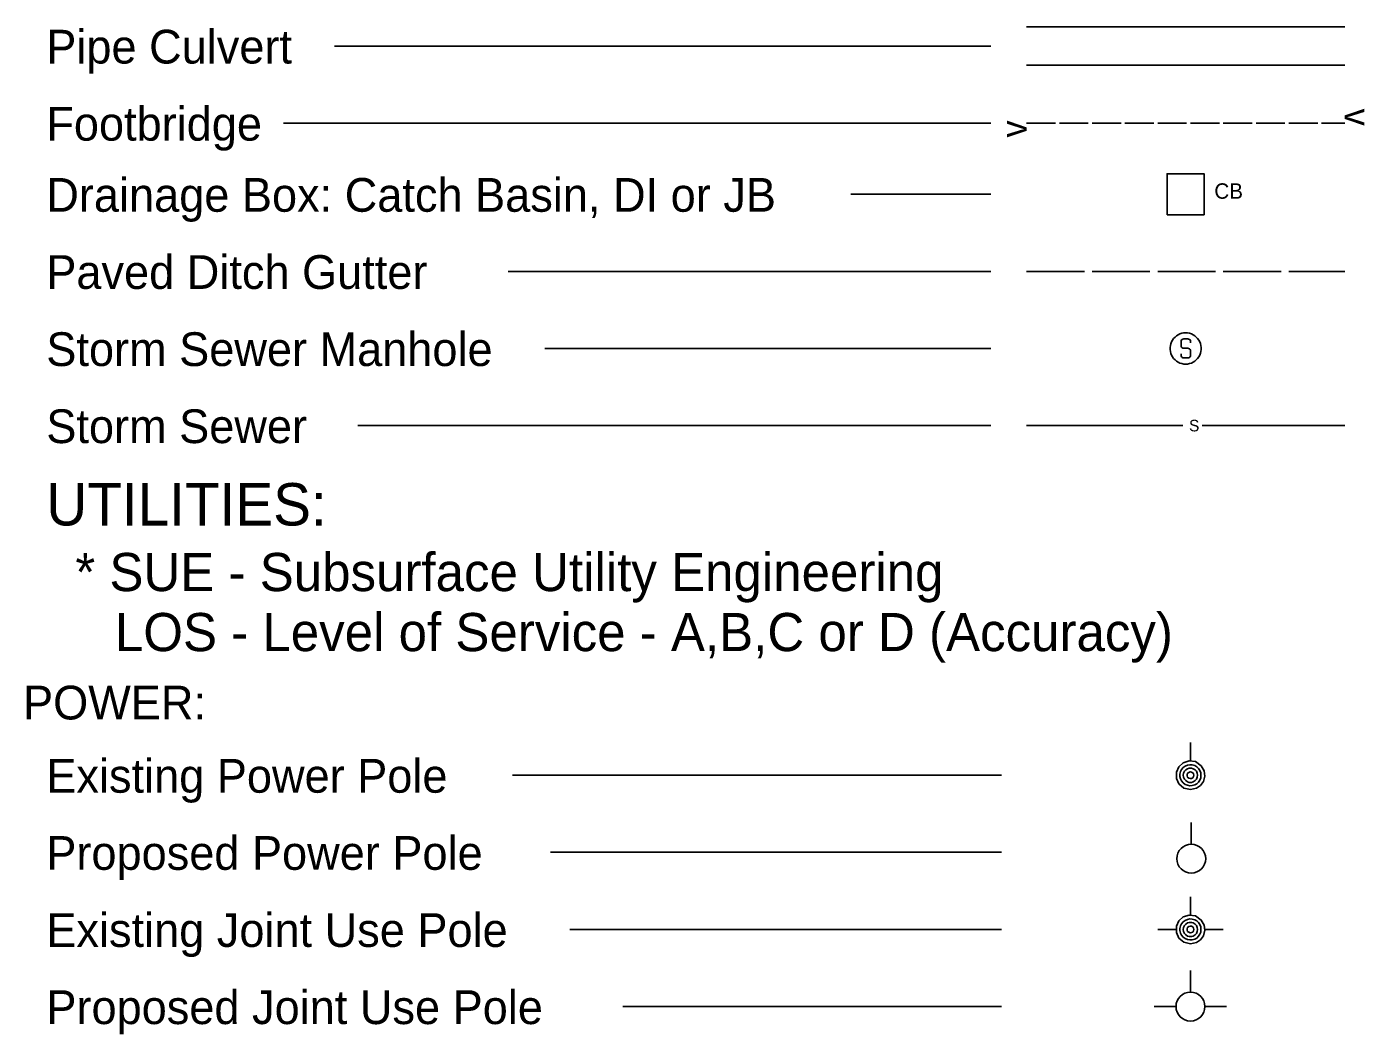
# Model space of a CAD drawing. Extents: x 1855058 to 1858918, y 1540202 to 1542502.
# Drawn here: x 1858001.4 to 1858351.4, y 1541960.3 to 1542223.9 of the extents above; entities that cross this region are included whole.
import ezdxf

# ---------------------------------------------------------------- set-up
doc = ezdxf.new("R2010")
doc.units = 0
doc.layers.add('Sheet Data Field CELL', color=7, linetype='Continuous')

msp = doc.modelspace()

# ---------------------------------------------------------------- linework, layer by layer
at = {"layer": 'Sheet Data Field CELL'}
for p, q in [((1858263.04, 1542223.9), (1858346.27, 1542223.9)), ((1858253.65, 1542218.85), (1858081.94, 1542218.85)), ((1858263.04, 1542213.81), (1858346.27, 1542213.81)), ((1858253.65, 1542198.67), (1858068.54, 1542198.67)), ((1858263.04, 1542198.67), (1858270.6, 1542198.67)), ((1858271.61, 1542198.67), (1858279.18, 1542198.67)), ((1858280.19, 1542198.67), (1858287.76, 1542198.67)), ((1858288.76, 1542198.67), (1858296.33, 1542198.67)), ((1858297.34, 1542198.67), (1858304.91, 1542198.67)), ((1858305.92, 1542198.67), (1858313.48, 1542198.67)), ((1858314.49, 1542198.67), (1858322.06, 1542198.67)), ((1858323.07, 1542198.67), (1858330.64, 1542198.67)), ((1858331.64, 1542198.67), (1858339.21, 1542198.67)), ((1858340.22, 1542198.67), (1858346.27, 1542198.67)), ((1858253.65, 1542180.07), (1858217.04, 1542180.07)), ((1858253.65, 1542159.89), (1858127.35, 1542159.89)), ((1858263.04, 1542159.89), (1858278.17, 1542159.89)), ((1858280.19, 1542159.89), (1858295.32, 1542159.89)), ((1858297.34, 1542159.89), (1858312.47, 1542159.89)), ((1858314.49, 1542159.89), (1858329.63, 1542159.89)), ((1858331.64, 1542159.89), (1858346.27, 1542159.89)), ((1858304.16, 1542142.24), (1858305.25, 1542142.24)), ((1858253.65, 1542139.72), (1858136.94, 1542139.72)), ((1858303.44, 1542140.44), (1858303.44, 1542141.52)), ((1858305.25, 1542139.75), (1858304.16, 1542139.75)), ((1858305.93, 1542141.52), (1858305.93, 1542141.16)), ((1858305.93, 1542137.95), (1858305.93, 1542139.06)), ((1858303.44, 1542138.31), (1858303.44, 1542137.95)), ((1858304.16, 1542137.26), (1858305.25, 1542137.26)), ((1858253.65, 1542119.54), (1858087.99, 1542119.54)), ((1858263.04, 1542119.54), (1858303.92, 1542119.54)), ((1858308.97, 1542119.54), (1858346.27, 1542119.54)), ((1858305.92, 1542031.77), (1858305.92, 1542036.61)), ((1858256.47, 1542028.04), (1858128.47, 1542028.04)), ((1858306.13, 1542010), (1858306.13, 1542015.67)), ((1858256.47, 1542007.87), (1858138.44, 1542007.87)), ((1858305.92, 1541991.41), (1858305.92, 1541996.25)), ((1858256.47, 1541987.69), (1858143.55, 1541987.69)), ((1858302.19, 1541987.69), (1858297.35, 1541987.69)), ((1858309.64, 1541987.69), (1858314.48, 1541987.69)), ((1858305.92, 1541971.3), (1858305.92, 1541976.98)), ((1858256.47, 1541967.51), (1858157.36, 1541967.51)), ((1858302.13, 1541967.52), (1858296.46, 1541967.52)), ((1858309.7, 1541967.52), (1858315.37, 1541967.52))]:
    msp.add_line(p, q, dxfattribs=at)
for points in [[(1858299.8, 1542174.71), (1858309.5, 1542174.71), (1858309.5, 1542185.45), (1858299.8, 1542185.45)], [(1858305.92, 1542024.32), (1858307.48, 1542024.62), (1858308.52, 1542025.36), (1858309.34, 1542026.41), (1858309.64, 1542027.82), (1858309.49, 1542029.16), (1858308.75, 1542030.5), (1858307.26, 1542031.62), (1858305.54, 1542031.77), (1858304.05, 1542031.32), (1858302.86, 1542030.28), (1858302.27, 1542028.86), (1858302.27, 1542027.22), (1858302.86, 1542025.81), (1858304.2, 1542024.69)], [(1858305.92, 1541983.96), (1858307.48, 1541984.26), (1858308.52, 1541985.01), (1858309.34, 1541986.05), (1858309.64, 1541987.46), (1858309.49, 1541988.8), (1858308.75, 1541990.14), (1858307.26, 1541991.26), (1858305.54, 1541991.41), (1858304.05, 1541990.96), (1858302.86, 1541989.92), (1858302.27, 1541988.51), (1858302.27, 1541986.87), (1858302.86, 1541985.45), (1858304.2, 1541984.33)]]:
    msp.add_lwpolyline(points, close=True, dxfattribs=at)
for points in [[(1858304.65, 1542143.81), (1858304.13, 1542143.78), (1858303.64, 1542143.68), (1858303.15, 1542143.52), (1858302.69, 1542143.29), (1858302.26, 1542143.02), (1858301.87, 1542142.7), (1858301.51, 1542142.3), (1858301.21, 1542141.91), (1858300.95, 1542141.45), (1858300.79, 1542140.96), (1858300.66, 1542140.47), (1858300.59, 1542139.98), (1858300.59, 1542139.45), (1858300.66, 1542138.96), (1858300.79, 1542138.44), (1858300.95, 1542137.98), (1858301.21, 1542137.52), (1858301.51, 1542137.13), (1858301.87, 1542136.73), (1858302.26, 1542136.41), (1858302.69, 1542136.14), (1858303.15, 1542135.91), (1858303.64, 1542135.75), (1858304.16, 1542135.65), (1858304.65, 1542135.62), (1858305.18, 1542135.65), (1858305.67, 1542135.75), (1858306.16, 1542135.91), (1858306.62, 1542136.14), (1858307.05, 1542136.41), (1858307.44, 1542136.73), (1858307.8, 1542137.13), (1858308.1, 1542137.52), (1858308.36, 1542137.98), (1858308.52, 1542138.47), (1858308.65, 1542138.96), (1858308.72, 1542139.45), (1858308.72, 1542139.98), (1858308.65, 1542140.47), (1858308.52, 1542140.99), (1858308.36, 1542141.45), (1858308.1, 1542141.91), (1858307.8, 1542142.3), (1858307.44, 1542142.7), (1858307.05, 1542143.02), (1858306.62, 1542143.29), (1858306.16, 1542143.52), (1858305.67, 1542143.68), (1858305.15, 1542143.78), (1858304.65, 1542143.81)], [(1858303.44, 1542141.52), (1858303.51, 1542141.75), (1858303.61, 1542141.94), (1858303.74, 1542142.07), (1858303.93, 1542142.17), (1858304.16, 1542142.24)], [(1858305.25, 1542142.24), (1858305.44, 1542142.17), (1858305.64, 1542142.07), (1858305.8, 1542141.94), (1858305.9, 1542141.75), (1858305.93, 1542141.52)], [(1858304.16, 1542139.75), (1858303.93, 1542139.78), (1858303.74, 1542139.88), (1858303.61, 1542140.04), (1858303.51, 1542140.24), (1858303.44, 1542140.44)], [(1858305.93, 1542139.03), (1858305.9, 1542139.26), (1858305.8, 1542139.45), (1858305.64, 1542139.62), (1858305.44, 1542139.72), (1858305.25, 1542139.75)], [(1858303.44, 1542137.98), (1858303.51, 1542137.75), (1858303.61, 1542137.55), (1858303.74, 1542137.39), (1858303.93, 1542137.29), (1858304.16, 1542137.26)], [(1858305.25, 1542137.26), (1858305.44, 1542137.29), (1858305.64, 1542137.39), (1858305.8, 1542137.55), (1858305.9, 1542137.75), (1858305.93, 1542137.98)], [(1858308.67, 1542028.04), (1858308.6, 1542028.71), (1858308.37, 1542029.31), (1858308, 1542029.83), (1858307.55, 1542030.28), (1858307.03, 1542030.58), (1858306.36, 1542030.73), (1858305.77, 1542030.8), (1858305.1, 1542030.65), (1858304.5, 1542030.43), (1858304.05, 1542030.06), (1858303.61, 1542029.53), (1858303.31, 1542029.01), (1858303.16, 1542028.34), (1858303.16, 1542027.75), (1858303.31, 1542027.08), (1858303.61, 1542026.55), (1858304.05, 1542026.03), (1858304.5, 1542025.66), (1858305.1, 1542025.44), (1858305.77, 1542025.29), (1858306.36, 1542025.36), (1858307.03, 1542025.51), (1858307.55, 1542025.81), (1858308, 1542026.26), (1858308.37, 1542026.78), (1858308.6, 1542027.37), (1858308.67, 1542028.04)], [(1858307.78, 1542028.04), (1858307.7, 1542028.57), (1858307.48, 1542029.09), (1858307.11, 1542029.46), (1858306.66, 1542029.76), (1858306.21, 1542029.91), (1858305.62, 1542029.91), (1858305.17, 1542029.76), (1858304.72, 1542029.46), (1858304.35, 1542029.09), (1858304.13, 1542028.57), (1858304.05, 1542028.04), (1858304.13, 1542027.52), (1858304.35, 1542027), (1858304.72, 1542026.63), (1858305.17, 1542026.33), (1858305.62, 1542026.18), (1858306.21, 1542026.18), (1858306.66, 1542026.33), (1858307.11, 1542026.63), (1858307.48, 1542027), (1858307.7, 1542027.52), (1858307.78, 1542028.04)], [(1858306.81, 1542028.04), (1858306.74, 1542028.42), (1858306.51, 1542028.71), (1858306.21, 1542028.86), (1858305.84, 1542028.94), (1858305.47, 1542028.79), (1858305.17, 1542028.57), (1858305.02, 1542028.19), (1858305.02, 1542027.89), (1858305.17, 1542027.52), (1858305.47, 1542027.3), (1858305.84, 1542027.15), (1858306.21, 1542027.22), (1858306.51, 1542027.37), (1858306.74, 1542027.67), (1858306.81, 1542028.04)], [(1858308.67, 1541987.69), (1858308.6, 1541988.36), (1858308.37, 1541988.95), (1858308, 1541989.47), (1858307.55, 1541989.92), (1858307.03, 1541990.22), (1858306.36, 1541990.37), (1858305.77, 1541990.44), (1858305.1, 1541990.29), (1858304.5, 1541990.07), (1858304.05, 1541989.7), (1858303.61, 1541989.18), (1858303.31, 1541988.65), (1858303.16, 1541987.98), (1858303.16, 1541987.39), (1858303.31, 1541986.72), (1858303.61, 1541986.2), (1858304.05, 1541985.68), (1858304.5, 1541985.3), (1858305.1, 1541985.08), (1858305.77, 1541984.93), (1858306.36, 1541985.01), (1858307.03, 1541985.15), (1858307.55, 1541985.45), (1858308, 1541985.9), (1858308.37, 1541986.42), (1858308.6, 1541987.02), (1858308.67, 1541987.69)], [(1858307.78, 1541987.69), (1858307.7, 1541988.21), (1858307.48, 1541988.73), (1858307.11, 1541989.1), (1858306.66, 1541989.4), (1858306.21, 1541989.55), (1858305.62, 1541989.55), (1858305.17, 1541989.4), (1858304.72, 1541989.1), (1858304.35, 1541988.73), (1858304.13, 1541988.21), (1858304.05, 1541987.69), (1858304.13, 1541987.17), (1858304.35, 1541986.65), (1858304.72, 1541986.27), (1858305.17, 1541985.97), (1858305.62, 1541985.83), (1858306.21, 1541985.83), (1858306.66, 1541985.97), (1858307.11, 1541986.27), (1858307.48, 1541986.65), (1858307.7, 1541987.17), (1858307.78, 1541987.69)], [(1858306.81, 1541987.69), (1858306.74, 1541988.06), (1858306.51, 1541988.36), (1858306.21, 1541988.51), (1858305.84, 1541988.58), (1858305.47, 1541988.43), (1858305.17, 1541988.21), (1858305.02, 1541987.84), (1858305.02, 1541987.54), (1858305.17, 1541987.17), (1858305.47, 1541986.94), (1858305.84, 1541986.79), (1858306.21, 1541986.87), (1858306.51, 1541987.02), (1858306.74, 1541987.32), (1858306.81, 1541987.69)]]:
    msp.add_lwpolyline(points, dxfattribs=at)
for centre in [(1858306.13, 1542006.21), (1858305.92, 1541967.51)]:
    msp.add_circle(centre, 3.78, dxfattribs=at)

# ---------------------------------------------------------------- texts
for s, height, p in [('Pipe Culvert', 8.8282, (1858006.5, 1542214.27)), ('Footbridge', 8.828, (1858006.51, 1542194.1)), ('Drainage Box: Catch Basin, DI or JB', 8.8282, (1858006.51, 1542175.49)), ('CB', 4.036, (1858312.16, 1542178.89)), ('Paved Ditch Gutter', 8.8282, (1858006.51, 1542155.3)), ('Storm Sewer Manhole', 8.8282, (1858006.51, 1542135.12)), ('Storm Sewer', 8.8282, (1858006.51, 1542114.95)), ('S', 3.03, (1858305.54, 1542118.02)), ('UTILITIES:', 11.098, (1858006.5, 1542093.39)), ('* SUE - Subsurface Utility Engineering', 9.9885, (1858014.11, 1542076.22)), ('LOS - Level of Service - A,B,C or D (Accuracy) ', 9.9885, (1858024.46, 1542060.51)), ('POWER:', 8.828, (1858000.42, 1542042.64)), ('Existing Power Pole', 8.8282, (1858006.51, 1542023.47)), ('Proposed Power Pole', 8.8282, (1858006.51, 1542003.29)), ('Existing Joint Use Pole', 8.8282, (1858006.51, 1541983.12)), ('Proposed Joint Use Pole', 8.8282, (1858006.53, 1541962.93))]:
    msp.add_text(s, height=height, dxfattribs=at).set_placement(p)
for rotation, p in [(270.2409, (1858346.26, 1542202.44)), (89.7591, (1858263.02, 1542194.9))]:
    msp.add_text('v', height=6.66, rotation=rotation, dxfattribs=at).set_placement(p)

doc.saveas('drawing.dxf')
